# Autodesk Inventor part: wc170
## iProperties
Shininess: 64.0
Length Units: 11272
Angle Units: 11279
Time Units: 11290
Mass Units: 11286
Length Display Precision: 3
Angle Display Precision: 2
Compacted: True
Part Number: wc170
Document SubType Name: Modeling
Created: 2004-08
Designer: John Blackburn
Manufacturer: Standard
Standards Organization: Custom
Material: Phenolic
Density: 0.0
Volumn: 0.0
Area: 0.0
PropertySet Name: Model Information
Control State: 0
Master: False
Checked Out: False
Author: John Blackburn
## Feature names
1. Base1
